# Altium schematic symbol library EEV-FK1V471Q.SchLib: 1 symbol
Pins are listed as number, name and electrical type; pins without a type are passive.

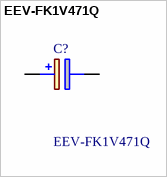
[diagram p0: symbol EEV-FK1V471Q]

## EEV-FK1V471Q
designator C?
Cap Aluminum Lytic 470uF 35V 20% (12.5 X 13.5mm) SMD 0.06 Ohm 1100mA 2000h 105C Automotive T/R; Manufacturer_Name: Panasonic; Geometry.Height: 15mm
footprint EEEFK0J332AQ
pins: 1 +, 2 -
